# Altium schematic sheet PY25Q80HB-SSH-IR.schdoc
size 127 x 101 mm
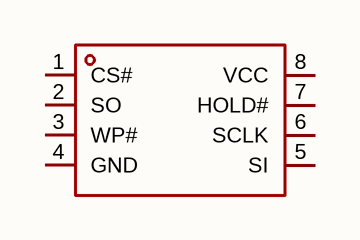
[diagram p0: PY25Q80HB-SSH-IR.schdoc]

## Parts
U?  py25q80hb-ssh-ir  [SOP-8_L4.9-W3.9-P1.27-LS6.0-BL]  (value not drawn)

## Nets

Not connected (* = marked no-connect by the designer): U? 1(CS#) 2(SO) 3(WP#) 4(GND) 5(SI) 6(SCLK) 7(HOLD#) 8(VCC)

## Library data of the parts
U? = py25q80hb-ssh-ir: Manufacturer: PUYA(普冉); AddInBom: yes; ModelId: 75c24a7891ee4dd6bdac16a7163ff87e; ModelName: SOP-8_L4.9-W3.9-P1.27-LS6.0-BL-1; ModelTransform: 192.913,236.22,0,0,0,0,-0.393,2.749,0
